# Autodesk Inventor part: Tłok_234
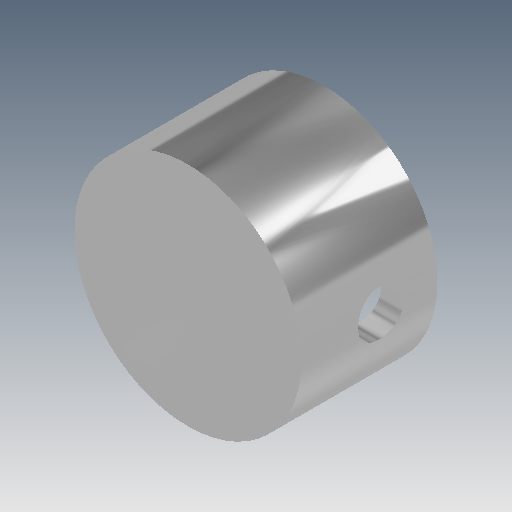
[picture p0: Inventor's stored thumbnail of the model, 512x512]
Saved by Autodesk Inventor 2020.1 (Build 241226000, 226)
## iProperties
Created: 2005-09
Part Number: Tłok_234
Document SubType Name: Modeling
Designer: F.Stasiak
Density: 1 g/cm^3
Material: Ogólny
Appearance: Chrom — polerowany
Manager: www.cadconsulting.pl
Company: Fabian Stasiak CAD Consulting
Author: F.Stasiak
Subject: Zbiór ćwiczeń. Autodesk Inventor 2020. Kurs podstawowy
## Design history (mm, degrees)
feature "Baza1"
node "Bryła1"
node "Korpusy bryłowe"
node "Korpusy powierzchniowe"
